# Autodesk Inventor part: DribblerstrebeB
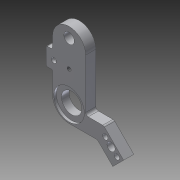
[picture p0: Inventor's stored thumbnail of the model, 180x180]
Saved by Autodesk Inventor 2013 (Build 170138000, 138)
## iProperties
Created: 2012-07
Part Number: DribblerstrebeB
Material: Aluminium 6061
Document SubType Name: Modeling
Designer: rYan
Mass: 4.21885 g
Surface Area: 15.9956 cm^2
Volume: 1.55677 cm^3
Density: 2.71 g/cm^3
d0: 12,000 mm
d2: 20,000 mm
d4: 120,00 grd
d5: 20,000 mm
d6: 20,000 mm
d7: 30,000 mm
d8: 4,000 mm
d9: 0,00 grd
d10: 6,000 mm
d17: 8,000 mm
d19: 12,000 mm
d20: 1,000 mm
d24: 4,000 mm
d25: 2,000 mm
Author: rYan
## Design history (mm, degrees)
node "DribblerstrebeA"
  sketch "Skizze1"
    geometry: L1 (-6.5, 26.5)-(11.124, 26.5) reference; L2 (11.124, 26.5)-(17.167, 32.543) reference; L3 (17.167, 32.543)-(21.41, 28.3) reference; L4 (21.41, 28.3)-(13.61, 20.5) reference; L5 (13.61, 20.5)-(6.5, 20.5) reference; L6 (6.5, 20.5)-(6.5, 0) reference; L7 (0, -17.628)-(0, 60.267) reference; L8 (27.513, 0)-(-15.206, 0) reference; L9 (-5.332, -6.5)-(6.5, -6.5) reference; L10 (13.632, 29.007)-(5.5, 37.139) reference; L11 (-6.5, 0)-(-6.5, 4) reference; L12 (-6.5, 12)-(-6.5, 26.5) reference; L13 (-9, 8)-(0, 8) reference; L14 (-7, 11.5)-(-8.5, 11.5) reference; L15 (-7, 4.5)-(-8.5, 4.5) reference; L16 (-9, 11)-(-9, 5) reference; C1 r 6.5 at (0, 20) reference; C2 r 6 at (0, 20) reference; C3 r 12 at (5.5, 37.139) reference; A1 r 6.5 centre (0, 0) between (-6.5, 0) and (6.5, 0) reference; A2 r 0.5 centre (-7, 12) between (-7, 11.5) and (-6.5, 12) reference; A3 r 0.5 centre (-7, 4) between (-6.5, 4) and (-7, 4.5) reference; A4 r 0.5 centre (-8.5, 11) between (-8.5, 11.5) and (-9, 11) reference; A5 r 0.5 centre (-8.5, 5) between (-9, 5) and (-8.5, 4.5) reference; 2 further points
  sketch "Skizze2"
    geometry: L1 (0, 40.352)-(0, -14.309) reference; L2 (6, -6.5)-(-6, -6.5) reference; A1 r 6.5 centre (0, 0) between (6.5, 0) and (-6.5, 0) reference; 2 further points
  sketch "Skizze3"
    geometry: L1 (-11.124, 26.5)-(6.5, 26.5) reference; L2 (6.5, 26.5)-(6.5, 0) reference; L3 (-6.5, 0)-(-6.5, 20.5) reference; L4 (-6.5, 20.5)-(-6.5, 26.5) reference; C1 r 6.5 at (0, 20) reference; 2 further points
feature "Volumenkörper1::DribblerstrebeA"
tag "Bezeichnung1"
node "Volumenkörper1"
other parameters: "d0" = 10, "d0_1" = 13, "d8" = 4, "d9" = 0, "d10" = 4.1, "d17" = 8, "d19" = 12, "d20" = 1, "d24" = 6
